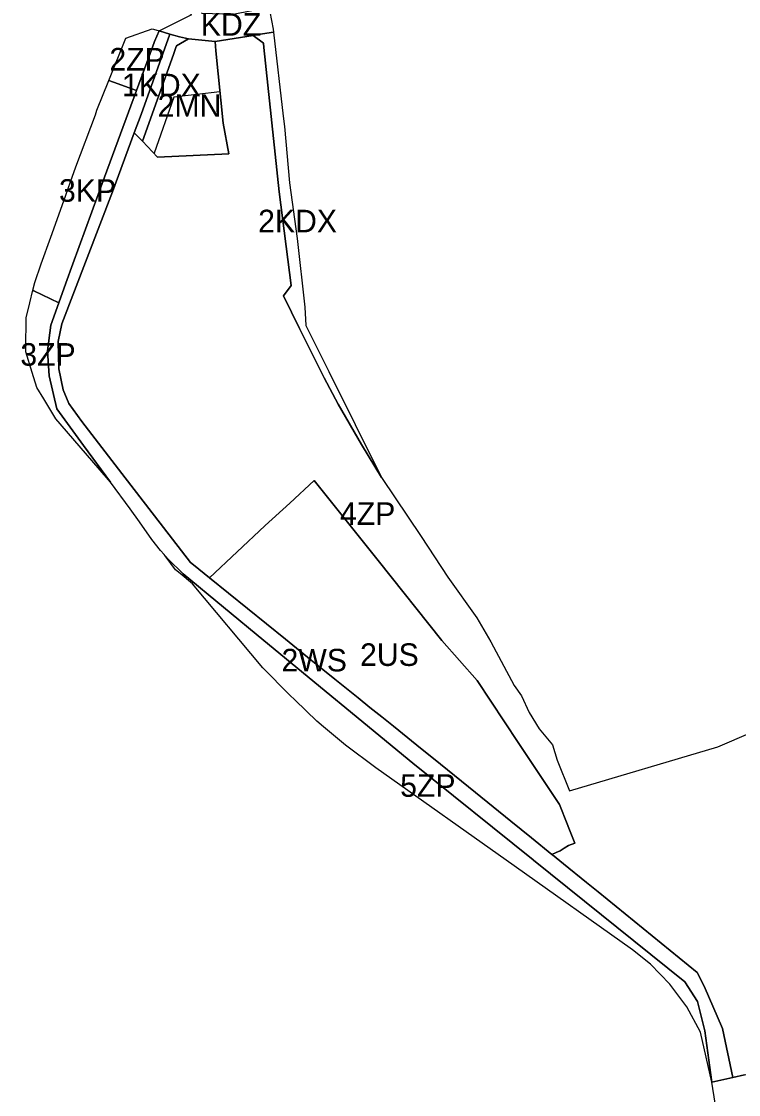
# Model space of a CAD drawing. Extents: x 7428426 to 7429844, y 5541841 to 5543687.
# Drawn here: x 7428886 to 7429267, y 5542703 to 5543274 of the extents above; entities that cross this region are included whole.
import ezdxf

# ---------------------------------------------------------------- set-up
doc = ezdxf.new("R2010")
doc.units = 0
for name, color, linetype in [('1', 7, 'Continuous'), ('linie_rozgraniczajace', 7, 'Continuous'), ('linie_zabudowy_nieprzekraczalne', 7, 'Continuous'), ('oznaczenia_przeznaczen', 7, 'Continuous')]:
    doc.layers.add(name, color=color, linetype=linetype)

msp = doc.modelspace()

# ---------------------------------------------------------------- linework, layer by layer
at = {"layer": '1'}
msp.add_lwpolyline([(7428991.2, 5543236.14), (7428966.77, 5543233.21), (7428956.21, 5543203.46)], dxfattribs=at)
at = {"layer": 'linie_rozgraniczajace'}
for points in [[(7428958.88, 5543268.54), (7428976.29, 5543277.15), (7428968.53, 5543280.57), (7428976.33, 5543278.2), (7428998.25, 5543277.39), (7429027.14, 5543283.11), (7429035.8, 5543284.82), (7429036.28, 5543282.45), (7429027.16, 5543280.59), (7429017.66, 5543278.65), (7429019.57, 5543269.36), (7429019.74, 5543267.89), (7429013.8, 5543266.94), (7429008.85, 5543266.14), (7429008.85, 5543266.14), (7428988.62, 5543262.92), (7428974.43, 5543264.27), (7428969.67, 5543265.28), (7428964.68, 5543266.79)], [(7428958.88, 5543268.54), (7428976.29, 5543277.15), (7428968.53, 5543280.57), (7428976.33, 5543278.2), (7428998.25, 5543277.39), (7429027.14, 5543283.11), (7429035.8, 5543284.82), (7429036.28, 5543282.45), (7429027.16, 5543280.59), (7429017.66, 5543278.65), (7429019.57, 5543269.36), (7429019.74, 5543267.89), (7429013.8, 5543266.94), (7429008.85, 5543266.14), (7429008.85, 5543266.14), (7428988.62, 5543262.92), (7428974.43, 5543264.27), (7428969.67, 5543265.28), (7428964.68, 5543266.79)], [(7428899.55, 5543098.52), (7428901.32, 5543112.08), (7428905.61, 5543124.05), (7428909.31, 5543134.38), (7428913.01, 5543144.71), (7428929.95, 5543190.76), (7428946.88, 5543236.81), (7428955.38, 5543259.91), (7428956.45, 5543262.83), (7428958.88, 5543268.54), (7428964.68, 5543266.79), (7428949.32, 5543224.15), (7428945.72, 5543214.38), (7428934.17, 5543183.03), (7428907.14, 5543112.8), (7428905.3, 5543103.42), (7428905.57, 5543088.94), (7428907.88, 5543077.77), (7428910.94, 5543070.56), (7428917.8, 5543060.91), (7428939.09, 5543033.29), (7428975.57, 5542985.96), (7428977.15, 5542984.68), (7428985.6, 5542977.86), (7428995.69, 5542969.69), (7429005.79, 5542961.52), (7429015.89, 5542953.35), (7429025.99, 5542945.19), (7429039.71, 5542934.14), (7429045.95, 5542929.12), (7429052.2, 5542924.09), (7429058.44, 5542919.06), (7429064.69, 5542914.04), (7429070.93, 5542909.01), (7429077.18, 5542903.98), (7429083.42, 5542898.95), (7429095.92, 5542888.9), (7429108.41, 5542878.84), (7429127.12, 5542863.73), (7429145.83, 5542848.63), (7429156.74, 5542839.74), (7429167.66, 5542830.85), (7429167.88, 5542830.67), (7429173.78, 5542825.87), (7429186.03, 5542815.89), (7429192.15, 5542810.91), (7429244.81, 5542768.15), (7429248.52, 5542760.84), (7429258.25, 5542738.4), (7429263.73, 5542712.35), (7429263.73, 5542712.33), (7429252.71, 5542709.77), (7429248.89, 5542737.17), (7429245.09, 5542752.67), (7429238.32, 5542763.08), (7429157.93, 5542827.78), (7429157.62, 5542828.03), (7429093.77, 5542879.41), (7429014.64, 5542944.61), (7428971.65, 5542980.02), (7428971.56, 5542980.1), (7428963.93, 5542987.67), (7428963.93, 5542987.67), (7428962.1, 5542989.49), (7428961.52, 5542990.26), (7428959.68, 5542992.36), (7428955.12, 5542998.31), (7428948.52, 5543007.54), (7428943.52, 5543014.53), (7428932.98, 5543028.74), (7428933.02, 5543028.77), (7428918.76, 5543048.2), (7428904.5, 5543067.62), (7428900.51, 5543085.18)], [(7428899.55, 5543098.52), (7428901.32, 5543112.08), (7428905.61, 5543124.05), (7428909.31, 5543134.38), (7428913.01, 5543144.71), (7428929.95, 5543190.76), (7428946.88, 5543236.81), (7428955.38, 5543259.91), (7428956.45, 5543262.83), (7428958.88, 5543268.54), (7428964.68, 5543266.79), (7428949.32, 5543224.15), (7428945.72, 5543214.38), (7428934.17, 5543183.03), (7428907.14, 5543112.8), (7428905.3, 5543103.42), (7428905.57, 5543088.94), (7428907.88, 5543077.77), (7428910.94, 5543070.56), (7428917.8, 5543060.91), (7428939.09, 5543033.29), (7428975.57, 5542985.96), (7428977.15, 5542984.68), (7428985.6, 5542977.86), (7428995.69, 5542969.69), (7429005.79, 5542961.52), (7429015.89, 5542953.35), (7429025.99, 5542945.19), (7429039.71, 5542934.14), (7429045.95, 5542929.12), (7429052.2, 5542924.09), (7429058.44, 5542919.06), (7429064.69, 5542914.04), (7429070.93, 5542909.01), (7429077.18, 5542903.98), (7429083.42, 5542898.95), (7429095.92, 5542888.9), (7429108.41, 5542878.84), (7429127.12, 5542863.73), (7429145.83, 5542848.63), (7429156.74, 5542839.74), (7429167.66, 5542830.85), (7429167.88, 5542830.67), (7429173.78, 5542825.87), (7429186.03, 5542815.89), (7429192.15, 5542810.91), (7429244.81, 5542768.15), (7429248.52, 5542760.84), (7429258.25, 5542738.4), (7429263.73, 5542712.35), (7429263.73, 5542712.33), (7429252.71, 5542709.77), (7429248.89, 5542737.17), (7429245.09, 5542752.67), (7429238.32, 5542763.08), (7429157.93, 5542827.78), (7429157.62, 5542828.03), (7429093.77, 5542879.41), (7429014.64, 5542944.61), (7428971.65, 5542980.02), (7428971.56, 5542980.1), (7428963.93, 5542987.67), (7428963.93, 5542987.67), (7428962.1, 5542989.49), (7428961.52, 5542990.26), (7428959.68, 5542992.36), (7428955.12, 5542998.31), (7428948.52, 5543007.54), (7428943.52, 5543014.53), (7428932.98, 5543028.74), (7428933.02, 5543028.77), (7428918.76, 5543048.2), (7428904.5, 5543067.62), (7428900.51, 5543085.18)], [(7428932.15, 5543242.14), (7428941.14, 5543264.7), (7428955.18, 5543269.67), (7428957.17, 5543269.08), (7428958.88, 5543268.54), (7428956.45, 5543262.83), (7428955.38, 5543259.91), (7428946.88, 5543236.81), (7428934.65, 5543241.24)], [(7428932.15, 5543242.14), (7428941.14, 5543264.7), (7428955.18, 5543269.67), (7428957.17, 5543269.08), (7428958.88, 5543268.54), (7428956.45, 5543262.83), (7428955.38, 5543259.91), (7428946.88, 5543236.81), (7428934.65, 5543241.24)], [(7428945.72, 5543214.38), (7428949.32, 5543224.15), (7428964.68, 5543266.79), (7428969.67, 5543265.28), (7428974.43, 5543264.27), (7428968.09, 5543260.61), (7428967.97, 5543260.25), (7428966.46, 5543255.97), (7428950, 5543209.87)], [(7428945.72, 5543214.38), (7428949.32, 5543224.15), (7428964.68, 5543266.79), (7428969.67, 5543265.28), (7428974.43, 5543264.27), (7428968.09, 5543260.61), (7428967.97, 5543260.25), (7428966.46, 5543255.97), (7428950, 5543209.87)], [(7429008.85, 5543266.14), (7429013.8, 5543266.94), (7429019.74, 5543267.89), (7429024.85, 5543223.13), (7429025.47, 5543217.65), (7429028.12, 5543187.8), (7429032.26, 5543158.17), (7429036.42, 5543121.78), (7429036.91, 5543111.94), (7429049.01, 5543087.43), (7429077.11, 5543031.15), (7429066.48, 5543048.65), (7429054.02, 5543070.16), (7429046.57, 5543084.11), (7429033.56, 5543110.35), (7429024.96, 5543127.7), (7429029.07, 5543133.21), (7429022.74, 5543182.98), (7429014.6, 5543259.68), (7429014.35, 5543262.06)], [(7429008.85, 5543266.14), (7429013.8, 5543266.94), (7429019.74, 5543267.89), (7429024.85, 5543223.13), (7429025.47, 5543217.65), (7429028.12, 5543187.8), (7429032.26, 5543158.17), (7429036.42, 5543121.78), (7429036.91, 5543111.94), (7429049.01, 5543087.43), (7429077.11, 5543031.15), (7429066.48, 5543048.65), (7429054.02, 5543070.16), (7429046.57, 5543084.11), (7429033.56, 5543110.35), (7429024.96, 5543127.7), (7429029.07, 5543133.21), (7429022.74, 5543182.98), (7429014.6, 5543259.68), (7429014.35, 5543262.06)], [(7428950, 5543209.87), (7428966.46, 5543255.97), (7428967.97, 5543260.25), (7428968.09, 5543260.61), (7428974.43, 5543264.27), (7428988.62, 5543262.92), (7428989.12, 5543257.93), (7428992.97, 5543219.42), (7428995.94, 5543203.19), (7428958.13, 5543201.46)], [(7428950, 5543209.87), (7428966.46, 5543255.97), (7428967.97, 5543260.25), (7428968.09, 5543260.61), (7428974.43, 5543264.27), (7428988.62, 5543262.92), (7428989.12, 5543257.93), (7428992.97, 5543219.42), (7428995.94, 5543203.19), (7428958.13, 5543201.46)], [(7428891.77, 5543130.68), (7428892.78, 5543134.79), (7428896.3, 5543144.66), (7428901.39, 5543158.92), (7428906.5, 5543173.27), (7428909.36, 5543181.26), (7428911.89, 5543188.37), (7428914.69, 5543196.21), (7428925.11, 5543223.92), (7428925.88, 5543226.41), (7428932.15, 5543242.14), (7428934.65, 5543241.24), (7428946.88, 5543236.81), (7428929.95, 5543190.76), (7428913.01, 5543144.71), (7428909.31, 5543134.38), (7428905.61, 5543124.05), (7428892.25, 5543130.45)], [(7428891.77, 5543130.68), (7428892.78, 5543134.79), (7428896.3, 5543144.66), (7428901.39, 5543158.92), (7428906.5, 5543173.27), (7428909.36, 5543181.26), (7428911.89, 5543188.37), (7428914.69, 5543196.21), (7428925.11, 5543223.92), (7428925.88, 5543226.41), (7428932.15, 5543242.14), (7428934.65, 5543241.24), (7428946.88, 5543236.81), (7428929.95, 5543190.76), (7428913.01, 5543144.71), (7428909.31, 5543134.38), (7428905.61, 5543124.05), (7428892.25, 5543130.45)], [(7428887.99, 5543097.92), (7428888.01, 5543099.69), (7428888.19, 5543115.97), (7428890.14, 5543123.97), (7428891.77, 5543130.68), (7428892.25, 5543130.45), (7428905.61, 5543124.05), (7428901.32, 5543112.08), (7428899.55, 5543098.52), (7428900.51, 5543085.18), (7428904.5, 5543067.62), (7428918.76, 5543048.2), (7428933.02, 5543028.77), (7428932.98, 5543028.74), (7428926.43, 5543036.38), (7428904.09, 5543062.42), (7428897.56, 5543073.04), (7428893.84, 5543079.08), (7428891.4, 5543086.95)], [(7428887.99, 5543097.92), (7428888.01, 5543099.69), (7428888.19, 5543115.97), (7428890.14, 5543123.97), (7428891.77, 5543130.68), (7428892.25, 5543130.45), (7428905.61, 5543124.05), (7428901.32, 5543112.08), (7428899.55, 5543098.52), (7428900.51, 5543085.18), (7428904.5, 5543067.62), (7428918.76, 5543048.2), (7428933.02, 5543028.77), (7428932.98, 5543028.74), (7428926.43, 5543036.38), (7428904.09, 5543062.42), (7428897.56, 5543073.04), (7428893.84, 5543079.08), (7428891.4, 5543086.95)], [(7428985.6, 5542977.86), (7429000.45, 5542991.76), (7429015.1, 5543005.47), (7429015.3, 5543005.66), (7429028.33, 5543017.62), (7429041.35, 5543029.59), (7429075.29, 5542987.1), (7429109.23, 5542944.6), (7429127.9, 5542923.29), (7429149.8, 5542890.31), (7429171.69, 5542857.34), (7429175.73, 5542847.08), (7429176.65, 5542844.76), (7429176.65, 5542844.76), (7429179.77, 5542836.82), (7429176.4, 5542835.53), (7429174.2, 5542834.18), (7429172, 5542832.84), (7429169.83, 5542831.85), (7429167.66, 5542830.85), (7429156.74, 5542839.74), (7429145.83, 5542848.63), (7429127.12, 5542863.73), (7429108.41, 5542878.84), (7429095.92, 5542888.9), (7429083.42, 5542898.95), (7429077.18, 5542903.98), (7429070.93, 5542909.01), (7429064.69, 5542914.04), (7429058.44, 5542919.06), (7429052.2, 5542924.09), (7429045.95, 5542929.12), (7429039.71, 5542934.14), (7429025.99, 5542945.19), (7429015.89, 5542953.35), (7429005.79, 5542961.52), (7428995.69, 5542969.69)], [(7428985.6, 5542977.86), (7429000.45, 5542991.76), (7429015.1, 5543005.47), (7429015.3, 5543005.66), (7429028.33, 5543017.62), (7429041.35, 5543029.59), (7429075.29, 5542987.1), (7429109.23, 5542944.6), (7429127.9, 5542923.29), (7429149.8, 5542890.31), (7429171.69, 5542857.34), (7429175.73, 5542847.08), (7429176.65, 5542844.76), (7429176.65, 5542844.76), (7429179.77, 5542836.82), (7429176.4, 5542835.53), (7429174.2, 5542834.18), (7429172, 5542832.84), (7429169.83, 5542831.85), (7429167.66, 5542830.85), (7429156.74, 5542839.74), (7429145.83, 5542848.63), (7429127.12, 5542863.73), (7429108.41, 5542878.84), (7429095.92, 5542888.9), (7429083.42, 5542898.95), (7429077.18, 5542903.98), (7429070.93, 5542909.01), (7429064.69, 5542914.04), (7429058.44, 5542919.06), (7429052.2, 5542924.09), (7429045.95, 5542929.12), (7429039.71, 5542934.14), (7429025.99, 5542945.19), (7429015.89, 5542953.35), (7429005.79, 5542961.52), (7428995.69, 5542969.69)], [(7428962.1, 5542989.49), (7428963.93, 5542987.67), (7428963.93, 5542987.67), (7428971.56, 5542980.1), (7428971.65, 5542980.02), (7429014.64, 5542944.61), (7429093.77, 5542879.41), (7429157.62, 5542828.03), (7429157.93, 5542827.78), (7429238.32, 5542763.08), (7429245.09, 5542752.67), (7429248.89, 5542737.17), (7429252.71, 5542709.77), (7429246.53, 5542736.42), (7429239.41, 5542749.91), (7429230.26, 5542761.92), (7429220.05, 5542772.57), (7429210.53, 5542780.17), (7429147.59, 5542824.76), (7429074.08, 5542876.83), (7429058.01, 5542888.95), (7429046.33, 5542898.71), (7429042.69, 5542901.76), (7429031.15, 5542912.89), (7429028.21, 5542915.72), (7429014.09, 5542930), (7428976.68, 5542974.61), (7428970.04, 5542980.08), (7428967.55, 5542982.14)], [(7428962.1, 5542989.49), (7428963.93, 5542987.67), (7428963.93, 5542987.67), (7428971.56, 5542980.1), (7428971.65, 5542980.02), (7429014.64, 5542944.61), (7429093.77, 5542879.41), (7429157.62, 5542828.03), (7429157.93, 5542827.78), (7429238.32, 5542763.08), (7429245.09, 5542752.67), (7429248.89, 5542737.17), (7429252.71, 5542709.77), (7429246.53, 5542736.42), (7429239.41, 5542749.91), (7429230.26, 5542761.92), (7429220.05, 5542772.57), (7429210.53, 5542780.17), (7429147.59, 5542824.76), (7429074.08, 5542876.83), (7429058.01, 5542888.95), (7429046.33, 5542898.71), (7429042.69, 5542901.76), (7429031.15, 5542912.89), (7429028.21, 5542915.72), (7429014.09, 5542930), (7428976.68, 5542974.61), (7428970.04, 5542980.08), (7428967.55, 5542982.14)], [(7429252.71, 5542709.77), (7429263.73, 5542712.33), (7429269.92, 5542713.77), (7429280.21, 5542716.17), (7429290.51, 5542718.57), (7429295.5, 5542719.72), (7429300.49, 5542720.88), (7429305.48, 5542722.04), (7429310.47, 5542723.2), (7429323.78, 5542673.23), (7429268.47, 5542660.17), (7429266.16, 5542659.62), (7429265.93, 5542659.56), (7429260.77, 5542658.35), (7429259, 5542669.65)], [(7429252.71, 5542709.77), (7429263.73, 5542712.33), (7429269.92, 5542713.77), (7429280.21, 5542716.17), (7429290.51, 5542718.57), (7429295.5, 5542719.72), (7429300.49, 5542720.88), (7429305.48, 5542722.04), (7429310.47, 5542723.2), (7429323.78, 5542673.23), (7429268.47, 5542660.17), (7429266.16, 5542659.62), (7429265.93, 5542659.56), (7429260.77, 5542658.35), (7429259, 5542669.65)]]:
    msp.add_lwpolyline(points, close=True, dxfattribs=at)
msp.add_lwpolyline([(7429269.92, 5542713.77), (7429263.73, 5542712.33), (7429263.73, 5542712.35), (7429258.25, 5542738.4), (7429248.52, 5542760.84), (7429244.81, 5542768.15), (7429192.15, 5542810.91), (7429186.03, 5542815.89), (7429173.78, 5542825.87), (7429167.88, 5542830.67), (7429167.66, 5542830.85), (7429169.83, 5542831.85), (7429172, 5542832.84), (7429174.2, 5542834.18), (7429176.4, 5542835.53), (7429179.77, 5542836.82), (7429176.65, 5542844.76), (7429176.65, 5542844.76), (7429175.73, 5542847.08), (7429171.69, 5542857.34), (7429149.8, 5542890.31), (7429127.9, 5542923.29), (7429109.23, 5542944.6), (7429075.29, 5542987.1), (7429041.35, 5543029.59), (7429028.33, 5543017.62), (7429015.3, 5543005.66), (7429015.1, 5543005.47), (7429000.45, 5542991.76), (7428985.6, 5542977.86), (7428977.15, 5542984.68), (7428975.57, 5542985.96), (7428939.09, 5543033.29), (7428917.8, 5543060.91), (7428910.94, 5543070.56), (7428907.88, 5543077.77), (7428905.57, 5543088.94), (7428905.3, 5543103.42), (7428907.14, 5543112.8), (7428934.17, 5543183.03), (7428945.72, 5543214.38), (7428950, 5543209.87), (7428958.13, 5543201.46), (7428995.94, 5543203.19), (7428992.97, 5543219.42), (7428989.12, 5543257.93), (7428988.62, 5543262.92), (7429008.85, 5543266.14), (7429008.85, 5543266.14), (7429014.35, 5543262.06), (7429014.6, 5543259.68), (7429022.74, 5543182.98), (7429029.07, 5543133.21), (7429024.96, 5543127.7), (7429033.56, 5543110.35), (7429046.57, 5543084.11), (7429054.02, 5543070.16), (7429066.48, 5543048.65), (7429077.11, 5543031.15), (7429098.25, 5542999.88), (7429112.36, 5542978.22), (7429127.66, 5542956.65), (7429135.1, 5542943.82), (7429147.63, 5542920.71), (7429151.47, 5542915.12), (7429155.49, 5542906.28), (7429160.9, 5542897.57), (7429167.95, 5542889.04), (7429170.5, 5542880.92), (7429176.92, 5542864.64), (7429255.76, 5542887.98), (7429273.48, 5542895.69)], dxfattribs=at)
msp.add_lwpolyline([(7429269.92, 5542713.77), (7429263.73, 5542712.33), (7429263.73, 5542712.35), (7429258.25, 5542738.4), (7429248.52, 5542760.84), (7429244.81, 5542768.15), (7429192.15, 5542810.91), (7429186.03, 5542815.89), (7429173.78, 5542825.87), (7429167.88, 5542830.67), (7429167.66, 5542830.85), (7429169.83, 5542831.85), (7429172, 5542832.84), (7429174.2, 5542834.18), (7429176.4, 5542835.53), (7429179.77, 5542836.82), (7429176.65, 5542844.76), (7429176.65, 5542844.76), (7429175.73, 5542847.08), (7429171.69, 5542857.34), (7429149.8, 5542890.31), (7429127.9, 5542923.29), (7429109.23, 5542944.6), (7429075.29, 5542987.1), (7429041.35, 5543029.59), (7429028.33, 5543017.62), (7429015.3, 5543005.66), (7429015.1, 5543005.47), (7429000.45, 5542991.76), (7428985.6, 5542977.86), (7428977.15, 5542984.68), (7428975.57, 5542985.96), (7428939.09, 5543033.29), (7428917.8, 5543060.91), (7428910.94, 5543070.56), (7428907.88, 5543077.77), (7428905.57, 5543088.94), (7428905.3, 5543103.42), (7428907.14, 5543112.8), (7428934.17, 5543183.03), (7428945.72, 5543214.38), (7428950, 5543209.87), (7428958.13, 5543201.46), (7428995.94, 5543203.19), (7428992.97, 5543219.42), (7428989.12, 5543257.93), (7428988.62, 5543262.92), (7429008.85, 5543266.14), (7429008.85, 5543266.14), (7429014.35, 5543262.06), (7429014.6, 5543259.68), (7429022.74, 5543182.98), (7429029.07, 5543133.21), (7429024.96, 5543127.7), (7429033.56, 5543110.35), (7429046.57, 5543084.11), (7429054.02, 5543070.16), (7429066.48, 5543048.65), (7429077.11, 5543031.15), (7429098.25, 5542999.88), (7429112.36, 5542978.22), (7429127.66, 5542956.65), (7429135.1, 5542943.82), (7429147.63, 5542920.71), (7429151.47, 5542915.12), (7429155.49, 5542906.28), (7429160.9, 5542897.57), (7429167.95, 5542889.04), (7429170.5, 5542880.92), (7429176.92, 5542864.64), (7429255.76, 5542887.98), (7429273.48, 5542895.69)], dxfattribs=at)
at = {"layer": 'linie_zabudowy_nieprzekraczalne'}
msp.add_lwpolyline([(7428991.2, 5543236.14), (7428966.77, 5543233.21), (7428956.21, 5543203.46)], dxfattribs=at)
msp.add_lwpolyline([(7428991.2, 5543236.14), (7428966.77, 5543233.21), (7428956.21, 5543203.46)], dxfattribs=at)

# ---------------------------------------------------------------- texts
at = {"layer": 'oznaczenia_przeznaczen'}
for s, p in [('KDZ', (7428981.08, 5543265.95)), ('KDZ', (7428981.08, 5543265.95)), ('KDZ', (7428981.08, 5543265.95)), ('KDZ', (7428981.08, 5543265.95)), ('2ZP', (7428932.49, 5543247.44)), ('2ZP', (7428932.49, 5543247.44)), ('2ZP', (7428932.49, 5543247.44)), ('2ZP', (7428932.49, 5543247.44)), ('1KDX', (7428939.14, 5543233.77)), ('1KDX', (7428939.14, 5543233.77)), ('1KDX', (7428939.14, 5543233.77)), ('1KDX', (7428939.14, 5543233.77)), ('2MN', (7428958.12, 5543222.86)), ('2MN', (7428958.12, 5543222.86)), ('2MN', (7428958.12, 5543222.86)), ('2MN', (7428958.12, 5543222.86)), ('3KP', (7428905.69, 5543177.71)), ('3KP', (7428905.69, 5543177.71)), ('3KP', (7428905.69, 5543177.71)), ('3KP', (7428905.69, 5543177.71)), ('2KDX', (7429011.51, 5543161.47)), ('2KDX', (7429011.51, 5543161.47)), ('2KDX', (7429011.51, 5543161.47)), ('2KDX', (7429011.51, 5543161.47)), ('3ZP', (7428885.14, 5543090.57)), ('3ZP', (7428885.14, 5543090.57)), ('3ZP', (7428885.14, 5543090.57)), ('3ZP', (7428885.14, 5543090.57)), ('4ZP', (7429054.99, 5543006)), ('4ZP', (7429054.99, 5543006)), ('4ZP', (7429054.99, 5543006)), ('4ZP', (7429054.99, 5543006)), ('2US', (7429065.68, 5542931.04)), ('2US', (7429065.68, 5542931.04)), ('2US', (7429065.68, 5542931.04)), ('2US', (7429065.68, 5542931.04)), ('2WS', (7429023.95, 5542928.12)), ('2WS', (7429023.95, 5542928.12)), ('2WS', (7429023.95, 5542928.12)), ('2WS', (7429023.95, 5542928.12)), ('5ZP', (7429087, 5542861.49)), ('5ZP', (7429087, 5542861.49)), ('5ZP', (7429087, 5542861.49)), ('5ZP', (7429087, 5542861.49))]:
    msp.add_text(s, height=12, dxfattribs=at).set_placement(p)

doc.saveas('drawing.dxf')
